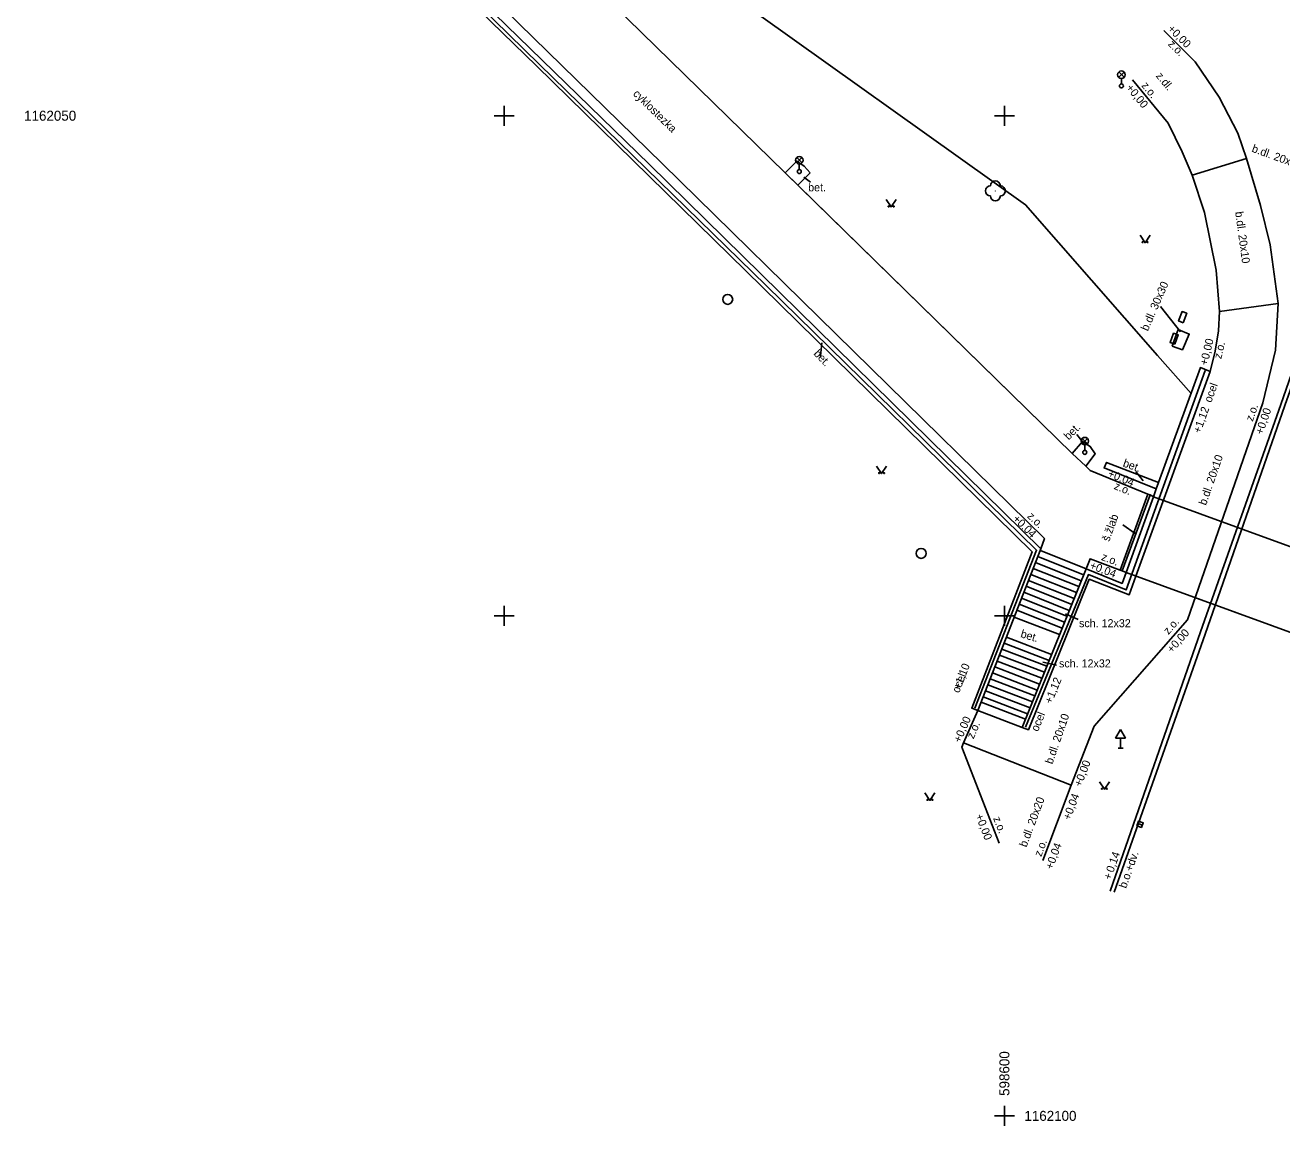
# Model space of a CAD drawing. Extents: x -598693 to -598360, y -1162453 to -1162007.
# Drawn here: x -598648.9 to -598586.1, y -1162100.5 to -1162045.5 of the extents above; entities that cross this region are included whole.
import ezdxf

# ---------------------------------------------------------------- set-up
doc = ezdxf.new("R2010")
doc.units = 0
for name, color, linetype in [('Vrstva 14', 7, 'Continuous'), ('Vrstva 15', 7, 'Continuous'), ('Vrstva 17', 7, 'Continuous'), ('Vrstva 19', 7, 'Continuous'), ('Vrstva 22', 7, 'Continuous'), ('Vrstva 25', 7, 'Continuous'), ('Vrstva 29', 7, 'Continuous'), ('Vrstva 41', 7, 'Continuous'), ('Vrstva 49', 7, 'Continuous'), ('Vrstva 50', 7, 'Continuous'), ('Vrstva 62', 7, 'Continuous'), ('Vrstva 63', 7, 'Continuous'), ('Vrstva 7', 7, 'Continuous')]:
    doc.layers.add(name, color=color, linetype=linetype)

msp = doc.modelspace()

# ---------------------------------------------------------------- linework, layer by layer
at = {"layer": 'Vrstva 14'}
for points in [[(-598605.91, -1162054.185), (-598605.66, -1162054.56), (-598605.41, -1162054.185)], [(-598593.22, -1162055.975), (-598592.97, -1162056.35), (-598592.72, -1162055.975)], [(-598606.39, -1162067.515), (-598606.14, -1162067.89), (-598605.89, -1162067.515)], [(-598595.25, -1162083.295), (-598595, -1162083.67), (-598594.75, -1162083.295)], [(-598603.97, -1162083.855), (-598603.72, -1162084.23), (-598603.47, -1162083.855)]]:
    msp.add_lwpolyline(points, dxfattribs=at)
for centre, radius in [((-598600.45, -1162053.76), 0.00025), ((-598605.785, -1162054.535), 0.025), ((-598605.535, -1162054.535), 0.025), ((-598593.095, -1162056.325), 0.025), ((-598592.845, -1162056.325), 0.025), ((-598606.265, -1162067.865), 0.025), ((-598606.015, -1162067.865), 0.025), ((-598595.125, -1162083.645), 0.025), ((-598594.875, -1162083.645), 0.025), ((-598603.845, -1162084.205), 0.025), ((-598603.595, -1162084.205), 0.025)]:
    msp.add_circle(centre, radius, dxfattribs=at)
for centre, start, end in [((-598600.7, -1162053.76), 89.99999, 269.99999), ((-598600.45, -1162053.51), 0, 179.99999), ((-598600.2, -1162053.76), 270, 89.99999), ((-598600.45, -1162054.01), 179.99999, 359.99999)]:
    msp.add_arc(centre, 0.25, start, end, dxfattribs=at)
at = {"layer": 'Vrstva 15'}
for points in [[(-598598.2, -1162071.74), (-598595.92, -1162072.65)], [(-598598.438, -1162072.334), (-598596.159, -1162073.244)], [(-598598.321, -1162072.036), (-598596.039, -1162072.947)], [(-598598.671, -1162072.93), (-598596.398, -1162073.838)], [(-598598.554, -1162072.632), (-598596.278, -1162073.541)], [(-598598.904, -1162073.526), (-598596.637, -1162074.431)], [(-598598.787, -1162073.228), (-598596.517, -1162074.134)], [(-598599.137, -1162074.122), (-598596.875, -1162075.025)], [(-598599.02, -1162073.824), (-598596.756, -1162074.728)], [(-598599.37, -1162074.718), (-598597.114, -1162075.619)], [(-598599.253, -1162074.42), (-598596.995, -1162075.322)], [(-598597.24, -1162075.933), (-598599.506, -1162075.065)], [(-598597.642, -1162076.931), (-598599.898, -1162076.067)], [(-598597.881, -1162077.525), (-598600.131, -1162076.663)], [(-598597.762, -1162077.228), (-598600.014, -1162076.365)], [(-598598.12, -1162078.119), (-598600.364, -1162077.26)], [(-598598, -1162077.822), (-598600.247, -1162076.962)], [(-598598.359, -1162078.713), (-598600.597, -1162077.856)], [(-598598.239, -1162078.416), (-598600.48, -1162077.558)], [(-598598.598, -1162079.306), (-598600.83, -1162078.452)], [(-598598.478, -1162079.009), (-598600.714, -1162078.154)], [(-598598.837, -1162079.9), (-598601.063, -1162079.048)], [(-598598.717, -1162079.603), (-598600.947, -1162078.75)], [(-598599.11, -1162080.58), (-598601.33, -1162079.73)], [(-598598.944, -1162080.167), (-598601.168, -1162079.316)]]:
    msp.add_lwpolyline(points, dxfattribs=at)
at = {"layer": 'Vrstva 17'}
msp.add_line((-598609.71, -1162052.85), (-598610.321, -1162053.475), dxfattribs=at)
for points in [[(-598601.33, -1162079.73), (-598601.63, -1162079.62), (-598598.61, -1162071.81), (-598612.11, -1162058.56), (-598623.38, -1162047.51), (-598634.13, -1162037.05), (-598633.84, -1162036.77)], [(-598598.17, -1162071.65), (-598617.74, -1162052.44), (-598633.84, -1162036.77)], [(-598610.96, -1162052.85), (-598610.38, -1162052.27), (-598610.01, -1162052.52), (-598609.71, -1162052.85)], [(-598596.62, -1162066.88), (-598596.09, -1162066.29), (-598595.71, -1162066.53), (-598595.46, -1162066.9), (-598595.93, -1162067.52)], [(-598592.3, -1162068.34), (-598594.89, -1162067.33), (-598595.02, -1162067.61), (-598592.41, -1162068.66)], [(-598601.33, -1162079.73), (-598598.17, -1162071.65)], [(-598593.91, -1162072.84), (-598594.12, -1162073.38), (-598595.92, -1162072.65), (-598599.11, -1162080.58)], [(-598593.422, -1162073.018), (-598593.76, -1162073.95), (-598595.76, -1162073.17), (-598598.8, -1162080.7), (-598599.11, -1162080.58)]]:
    msp.add_lwpolyline(points, dxfattribs=at)
at = {"layer": 'Vrstva 19'}
for p, q in [((-598594.19, -1162080.687), (-598594.44, -1162081.12)), ((-598594.44, -1162081.12), (-598593.94, -1162081.12)), ((-598594.19, -1162080.687), (-598593.94, -1162081.12)), ((-598594.19, -1162081.62), (-598594.19, -1162081.12)), ((-598594.315, -1162081.62), (-598594.065, -1162081.62))]:
    msp.add_line(p, q, dxfattribs=at)
at = {"layer": 'Vrstva 22'}
for points in [[(-598601.48, -1162079.62), (-598598.39, -1162071.72), (-598611.9, -1162058.48), (-598623.24, -1162047.44), (-598633.91, -1162036.98)], [(-598589.96, -1162062.73), (-598593.91, -1162073.71), (-598595.8, -1162072.94), (-598598.94, -1162080.57)]]:
    msp.add_lwpolyline(points, dxfattribs=at)
at = {"layer": 'Vrstva 25'}
msp.add_line((-598593.337, -1162085.376), (-598593.103, -1162085.464), dxfattribs=at)
for points in [[(-598594.21, -1162072.72), (-598592.83, -1162068.92)], [(-598594.11, -1162072.76), (-598592.72, -1162068.95)]]:
    msp.add_lwpolyline(points, dxfattribs=at)
msp.add_lwpolyline([(-598593.381, -1162085.493), (-598593.147, -1162085.581), (-598593.059, -1162085.347), (-598593.293, -1162085.259)], close=True, dxfattribs=at)
for centre in [(-598613.83, -1162059.18), (-598604.16, -1162071.88)]:
    msp.add_circle(centre, 0.25, dxfattribs=at)
at = {"layer": 'Vrstva 29'}
for p, q in [((-598594.282, -1162048.079), (-598594.018, -1162047.815)), ((-598594.014, -1162048.078), (-598594.278, -1162047.813)), ((-598594.15, -1162048.41), (-598594.15, -1162048.135)), ((-598610.382, -1162052.359), (-598610.118, -1162052.095)), ((-598610.114, -1162052.358), (-598610.378, -1162052.093)), ((-598610.25, -1162052.69), (-598610.25, -1162052.415)), ((-598596.112, -1162066.399), (-598595.848, -1162066.135)), ((-598595.844, -1162066.398), (-598596.108, -1162066.133)), ((-598595.98, -1162066.73), (-598595.98, -1162066.455))]:
    msp.add_line(p, q, dxfattribs=at)
for points in [[(-598591.059, -1162060.348), (-598590.886, -1162059.879), (-598591.121, -1162059.792), (-598591.294, -1162060.261)], [(-598591.48, -1162061.428), (-598591.306, -1162060.959), (-598591.54, -1162060.872), (-598591.714, -1162061.341)]]:
    msp.add_lwpolyline(points, close=True, dxfattribs=at)
for centre, radius in [((-598594.15, -1162047.948), 0.188), ((-598594.15, -1162048.51), 0.1), ((-598610.25, -1162052.228), 0.188), ((-598610.25, -1162052.79), 0.1), ((-598595.98, -1162066.268), 0.188), ((-598595.98, -1162066.83), 0.1)]:
    msp.add_circle(centre, radius, dxfattribs=at)
at = {"layer": 'Vrstva 41'}
msp.add_lwpolyline([(-598590.66, -1162063.89), (-598592.34, -1162061.98), (-598598.94, -1162054.45), (-598613.85, -1162043.81), (-598628.5, -1162032.23), (-598633.42, -1162029.9)], dxfattribs=at)
at = {"layer": 'Vrstva 49'}
for p, q in [((-598610.02, -1162053.08), (-598609.69, -1162053.32)), ((-598591.19, -1162060.81), (-598592.19, -1162059.54)), ((-598609.195, -1162062.021), (-598609.117, -1162061.359)), ((-598596.02, -1162066.4), (-598596.382, -1162065.932)), ((-598593.067, -1162068.249), (-598593.429, -1162067.78)), ((-598593.47, -1162070.88), (-598594.08, -1162070.45)), ((-598596.94, -1162074.91), (-598596.32, -1162075.18)), ((-598598.07, -1162077.31), (-598597.39, -1162077.46))]:
    msp.add_line(p, q, dxfattribs=at)
at = {"layer": 'Vrstva 62'}
for p, q in [((-598625, -1162050.5), (-598625, -1162049.5)), ((-598600, -1162050.5), (-598600, -1162049.5)), ((-598625.5, -1162050), (-598624.5, -1162050)), ((-598600.5, -1162050), (-598599.5, -1162050)), ((-598625, -1162075.5), (-598625, -1162074.5)), ((-598600, -1162075.5), (-598600, -1162074.5)), ((-598625.5, -1162075), (-598624.5, -1162075)), ((-598600.5, -1162075), (-598599.5, -1162075)), ((-598600.5, -1162100), (-598599.5, -1162100)), ((-598600, -1162100.5), (-598600, -1162099.5))]:
    msp.add_line(p, q, dxfattribs=at)
at = {"layer": 'Vrstva 63'}
for points in [[(-598566.432, -1162082.858), (-598593.91, -1162072.84), (-598594.11, -1162072.76), (-598594.21, -1162072.72), (-598595.72, -1162072.15), (-598595.92, -1162072.65), (-598598.2, -1162071.74), (-598598.17, -1162071.65), (-598598, -1162071.13), (-598617.09, -1162052.4), (-598636.45, -1162033.47)], [(-598624.59, -1162039.53), (-598610.96, -1162052.85), (-598610.321, -1162053.475), (-598596.62, -1162066.88), (-598595.93, -1162067.52), (-598595.72, -1162067.74), (-598592.83, -1162068.92), (-598592.72, -1162068.95), (-598592.55, -1162069.05), (-598560.62, -1162080.68)]]:
    msp.add_lwpolyline(points, dxfattribs=at)
at = {"layer": 'Vrstva 7'}
for points in [[(-598647.91, -1162012.03), (-598646.38, -1162013.97), (-598644.59, -1162016.41), (-598642.95, -1162018.93), (-598641.66, -1162021.6), (-598641.37, -1162022.35), (-598640.86, -1162023.52), (-598639.84, -1162024.59), (-598633.37, -1162030.92), (-598625.22, -1162038.92), (-598624.59, -1162039.53), (-598610.96, -1162052.85), (-598596.62, -1162066.88), (-598595.93, -1162067.52), (-598595.72, -1162067.74), (-598592.83, -1162068.92), (-598592.72, -1162068.95), (-598592.55, -1162069.05)], [(-598648.83, -1162016.78), (-598647.76, -1162018.45), (-598646.81, -1162020.2), (-598645.59, -1162022.96), (-598644.65, -1162024.73), (-598643.59, -1162026.42), (-598636.45, -1162033.47), (-598617.09, -1162052.4), (-598598, -1162071.13), (-598598.17, -1162071.65)], [(-598592.03, -1162045.74), (-598590.46, -1162047.31), (-598589.27, -1162049.08), (-598588.33, -1162050.88), (-598587.9, -1162052.14), (-598587.19, -1162054.48), (-598586.72, -1162056.46), (-598586.32, -1162059.38), (-598586.45, -1162061.72), (-598587.08, -1162064.36), (-598590.84, -1162075.21), (-598595.52, -1162080.52), (-598596.66, -1162083.47), (-598598.07, -1162087.24)], [(-598594.72, -1162088.76), (-598590.19, -1162075.81), (-598586.18, -1162064.43), (-598583.15, -1162055.72), (-598582.52, -1162053.91), (-598582.07, -1162052.62), (-598582.01, -1162052.39), (-598580.24, -1162047.36)], [(-598593.59, -1162048.2), (-598591.82, -1162050.38), (-598591.12, -1162051.81), (-598590.61, -1162052.97), (-598590, -1162054.83), (-598589.42, -1162057.72), (-598589.24, -1162059.78), (-598589.3, -1162060.76), (-598589.46, -1162061.77), (-598589.71, -1162062.79)], [(-598590.61, -1162052.97), (-598587.9, -1162052.14)], [(-598594.51, -1162088.82), (-598589.97, -1162075.92), (-598585.98, -1162064.49), (-598582.9, -1162055.82), (-598582.29, -1162054.04)], [(-598586.32, -1162059.38), (-598589.24, -1162059.78)], [(-598591.31, -1162060.69), (-598590.76, -1162060.92), (-598591.1, -1162061.7), (-598591.62, -1162061.52)], [(-598591.31, -1162060.69), (-598591.62, -1162061.52)], [(-598589.71, -1162062.79), (-598593.422, -1162073.018)], [(-598589.71, -1162062.79), (-598590.2, -1162062.59), (-598592.3, -1162068.34)], [(-598592.3, -1162068.34), (-598592.41, -1162068.66), (-598592.55, -1162069.05), (-598593.91, -1162072.84)], [(-598560.62, -1162080.68), (-598592.55, -1162069.05)], [(-598595.92, -1162072.65), (-598595.72, -1162072.15), (-598594.21, -1162072.72), (-598594.11, -1162072.76), (-598593.91, -1162072.84)], [(-598593.91, -1162072.84), (-598562.01, -1162084.47)], [(-598601.33, -1162079.73), (-598602.04, -1162081.35), (-598602.12, -1162081.57), (-598600.26, -1162086.36)], [(-598602.04, -1162081.35), (-598596.66, -1162083.47)]]:
    msp.add_lwpolyline(points, dxfattribs=at)

# ---------------------------------------------------------------- texts
at = {"layer": 'Vrstva 49'}
for s, rotation, p in [('z.o.', 315, (-598591.85, -1162046.45)), ('z.dl.', 309.07406, (-598592.449, -1162048.019)), ('z.o.', 309.07406, (-598593.172, -1162048.501)), ('cyklostezka', 315.64341, (-598618.593, -1162048.938)), ('b.dl. 20x10', 340.09153, (-598587.667, -1162051.796)), ('b.dl. 20x10', 277.80019, (-598588.467, -1162054.813)), ('b.dl. 30x30', 66.44774, (-598592.831, -1162060.796)), ('bet.', 314.21556, (-598609.564, -1162061.922)), ('z.o.', 76.2284, (-598589.162, -1162062.183)), ('ocel', 70.21406, (-598589.659, -1162064.37)), ('z.o.', 70.88656, (-598587.586, -1162065.309)), ('bet.', 44.88723, (-598596.79, -1162066.24)), ('bet.', 340.40484, (-598594.108, -1162067.524)), ('b.dl. 20x10', 70.88656, (-598589.922, -1162069.507)), ('z.o.', 337.78959, (-598594.553, -1162068.651)), ('z.o.', 315.54537, (-598598.886, -1162070.053)), ('š.žlab', 70.04111, (-598594.765, -1162071.318)), ('z.o.', 339.31931, (-598595.187, -1162072.202)), ('z.o.', 48.60847, (-598591.801, -1162075.966)), ('bet.', 343.12153, (-598599.222, -1162076.064)), ('ocel', 68.63758, (-598602.268, -1162078.89)), ('ocel', 67.6312, (-598598.323, -1162080.818)), ('b.dl. 20x10', 70.88656, (-598597.604, -1162082.447)), ('z.o.', 66.33353, (-598601.545, -1162081.182)), ('b.dl. 20x20', 69.49394, (-598598.898, -1162086.599)), ('z.o.', 291.22164, (-598600.57, -1162085.121)), ('z.o.', 69.49394, (-598598.159, -1162087.07)), ('b.o.+dv.', 70.61109, (-598593.915, -1162088.655))]:
    msp.add_text(s, height=0.4, rotation=rotation, dxfattribs=at).set_placement(p)
for s, p in [('bet.', (-598609.81, -1162053.78)), ('sch. 12x32', (-598596.27, -1162075.57)), ('sch. 12x32', (-598597.27, -1162077.58))]:
    msp.add_text(s, height=0.4, dxfattribs=at).set_placement(p)
at = {"layer": 'Vrstva 50'}
for s, rotation, p in [('+0,00', 315, (-598591.87, -1162045.69)), ('+0,00', 309.07406, (-598593.941, -1162048.613)), ('+0,00', 76.2284, (-598589.857, -1162062.509)), ('+1,12', 70.21406, (-598590.207, -1162065.907)), ('+0,00', 70.88656, (-598587.093, -1162065.971)), ('+0,04', 337.78959, (-598594.862, -1162068.033)), ('+0,04', 315.54537, (-598599.608, -1162070.188)), ('+0,04', 339.31931, (-598595.768, -1162072.633)), ('+0,00', 48.60847, (-598591.62, -1162076.887)), ('+1,10', 68.63758, (-598602.208, -1162078.735)), ('+1,12', 67.6312, (-598597.646, -1162079.432)), ('+0,00', 66.33353, (-598602.2, -1162081.377)), ('+0,00', 68.87144, (-598596.166, -1162083.577)), ('+0,04', 69.49394, (-598596.716, -1162085.245)), ('+0,00', 291.22164, (-598601.456, -1162084.992)), ('+0,04', 69.49394, (-598597.598, -1162087.713)), ('0,14', 70.61109, (-598594.556, -1162087.862)), ('+', 70.61109, (-598594.687, -1162088.233))]:
    msp.add_text(s, height=0.4, rotation=rotation, dxfattribs=at).set_placement(p)
at = {"layer": 'Vrstva 62'}
for s, p in [('1162050', (-598649, -1162050.25)), ('1162100', (-598599, -1162100.25))]:
    msp.add_text(s, height=0.5, dxfattribs=at).set_placement(p)
msp.add_text('598600', height=0.5, rotation=90, dxfattribs=at).set_placement((-598599.75, -1162099))

doc.saveas('drawing.dxf')
